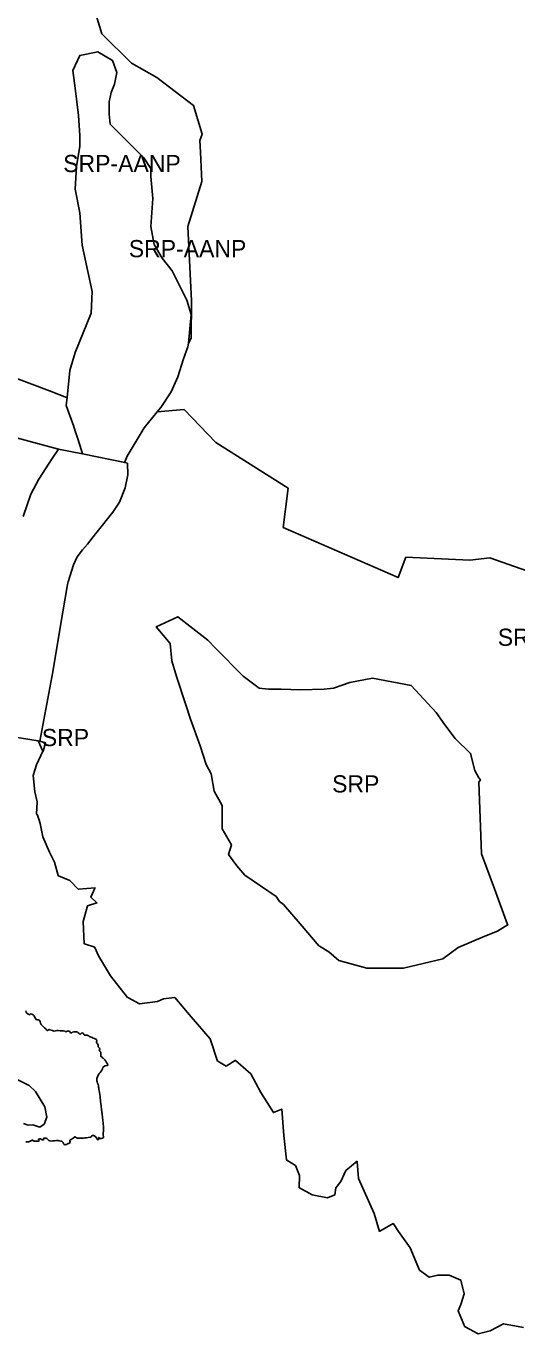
# Model space of a CAD drawing. Extents: x 598968 to 613553, y 4409678 to 4430833.
# Drawn here: x 602505 to 602848, y 4409678 to 4410591 of the extents above; entities that cross this region are included whole.
import ezdxf

# ---------------------------------------------------------------- set-up
doc = ezdxf.new("R2010")
doc.units = 0
for name, color, linetype in [('1', 7, 'Continuous'), ('Sòl Rústic Protegit', 7, 'Continuous'), ('Sòl Rústic Protegit - Alt Nivell de Protecció', 7, 'Continuous')]:
    doc.layers.add(name, color=color, linetype=linetype)

msp = doc.modelspace()

# ---------------------------------------------------------------- linework, layer by layer
at = {"layer": '1'}
for points in [[(602497.7035, 4410094.9206), (602513.6544, 4410092.2408), (602514.8283, 4410092.0436), (602523.893, 4410140.448), (602529.3381, 4410172.8446), (602533.8915, 4410200.156), (602534.0976, 4410201.3922), (602534.6887, 4410203.333), (602538.2975, 4410215.182), (602540.9874, 4410220.802), (602544.5974, 4410225.622), (602548.1209, 4410229.6975), (602553.7417, 4410236.921), (602554.8294, 4410238.3188), (602565.867, 4410252.0322), (602569.4816, 4410257.6212), (602570.4375, 4410259.0991), (602574.4065, 4410269.0133), (602576.2733, 4410278.0161), (602576.0051, 4410286.2359), (602574.1695, 4410286.6131), (602544.6902, 4410292.6714), (602527.955, 4410296.1106), (602523.5834, 4410289.4568), (602518.8825, 4410282.3021), (602514.1639, 4410275.1202), (602508.7008, 4410264.5001), (602503.3766, 4410249.1016)], [(602503.3766, 4410249.1016), (602508.7008, 4410264.5001), (602514.1639, 4410275.1202), (602518.8825, 4410282.3021), (602523.5834, 4410289.4568), (602527.955, 4410296.1106), (602498.704, 4410303.9698)], [(602505.1992, 4409812.3078), (602506.0392, 4409812.2679), (602506.9492, 4409812.3179), (602507.7192, 4409812.4779), (602508.5692, 4409813.0279), (602509.4491, 4409813.4279), (602509.6391, 4409813.4579), (602510.0891, 4409813.5079), (602510.2852, 4409813.3385), (602510.3091, 4409813.3179), (602510.5891, 4409812.7679), (602510.7619, 4409812.7466), (602511.3191, 4409812.678), (602512.199, 4409812.678), (602513.119, 4409812.698), (602513.659, 4409812.758), (602514.329, 4409812.898), (602514.239, 4409813.458), (602513.879, 4409813.788), (602513.929, 4409814.068), (602514.229, 4409814.178), (602514.949, 4409814.418), (602515.419, 4409814.3281), (602515.989, 4409813.9781), (602516.579, 4409813.7381), (602517.189, 4409813.6581), (602517.709, 4409813.8981), (602517.579, 4409814.4281), (602517.559, 4409814.6682), (602517.839, 4409814.7882), (602518.589, 4409814.9382), (602519.359, 4409814.9082), (602519.879, 4409814.5782), (602519.8928, 4409814.5611), (602520.449, 4409813.8782), (602521.139, 4409813.3182), (602521.2443, 4409813.268), (602521.7889, 4409813.0082), (602522.8289, 4409812.8483), (602523.8989, 4409812.9083), (602525.2488, 4409813.0883), (602526.5188, 4409813.2283), (602527.6588, 4409813.1383), (602528.4288, 4409812.9584), (602529.4688, 4409812.8384), (602530.3188, 4409812.6884), (602530.5273, 4409812.5308), (602530.7688, 4409812.3484), (602531.0788, 4409811.7485), (602531.4588, 4409810.8885), (602531.8788, 4409810.3585), (602532.0192, 4409810.3271), (602532.5487, 4409810.2085), (602533.1587, 4409810.4185), (602533.8287, 4409810.5085), (602534.1787, 4409810.7785), (602534.6587, 4409811.0085), (602535.1987, 4409811.0985), (602535.6687, 4409811.3985), (602535.9587, 4409812.1285), (602535.8487, 4409812.7885), (602535.7687, 4409813.3485), (602535.9887, 4409813.6285), (602536.4787, 4409813.7385), (602536.8387, 4409813.8885), (602537.5287, 4409814.2786), (602538.1787, 4409814.7887), (602539.3487, 4409815.8287), (602539.5666, 4409815.6398), (602539.6486, 4409815.5687), (602539.8333, 4409815.4574), (602540.3786, 4409815.1287), (602541.2086, 4409814.9088), (602542.1586, 4409814.8288), (602543.2586, 4409814.7688), (602544.3086, 4409814.8188), (602545.3486, 4409814.8488), (602546.3686, 4409814.9889), (602547.4686, 4409815.1389), (602548.5586, 4409815.2989), (602550.5185, 4409815.649), (602550.6685, 4409815.909), (602550.8785, 4409816.129), (602551.6785, 4409816.589), (602552.2485, 4409816.779), (602552.7085, 4409816.559), (602552.861, 4409816.4392), (602553.2684, 4409816.119), (602553.3397, 4409816.0917), (602553.7384, 4409815.939), (602553.8646, 4409815.8205), (602554.4084, 4409815.309), (602554.5484, 4409814.9291), (602554.7884, 4409814.379), (602555.1084, 4409813.889), (602555.5084, 4409813.599), (602555.5165, 4409813.6069), (602555.9484, 4409814.029), (602556.0684, 4409814.6191), (602555.8684, 4409815.1891), (602555.8784, 4409815.2891), (602555.9684, 4409815.2691), (602556.2033, 4409815.107), (602556.2584, 4409815.0691), (602556.7284, 4409814.7391), (602556.8387, 4409814.6698), (602557.1584, 4409814.469), (602557.7584, 4409814.5091), (602558.5784, 4409814.8092), (602559.2884, 4409815.2892), (602559.4084, 4409815.9092), (602559.2184, 4409816.9892), (602559.1884, 4409818.0092), (602559.1784, 4409818.4891), (602559.2484, 4409819.6191), (602559.3584, 4409820.6791), (602559.3784, 4409822.0991), (602559.3184, 4409823.329), (602559.1784, 4409824.609), (602559.0384, 4409825.699), (602558.9184, 4409826.689), (602558.8384, 4409827.759), (602558.7284, 4409828.829), (602558.6084, 4409829.8689), (602558.4384, 4409830.9389), (602558.3384, 4409831.9589), (602557.9284, 4409834.5088), (602557.6084, 4409837.4388), (602557.1784, 4409840.3787), (602556.9584, 4409843.9886), (602556.5884, 4409846.6686), (602556.4084, 4409847.7786), (602556.1784, 4409848.7486), (602555.9984, 4409849.6486), (602555.9184, 4409850.4985), (602555.7784, 4409851.3485), (602555.5084, 4409852.1985), (602555.2584, 4409853.2185), (602554.9284, 4409854.2284), (602554.6884, 4409854.8884), (602554.6184, 4409855.5184), (602554.7084, 4409856.5484), (602555.1384, 4409857.7384), (602555.5583, 4409858.7284), (602556.0483, 4409859.5784), (602556.3883, 4409859.9784), (602557.0683, 4409860.7984), (602557.7383, 4409861.6284), (602558.2182, 4409862.3884), (602558.5582, 4409863.2684), (602558.9582, 4409864.1584), (602560.2782, 4409865.4384), (602562.2082, 4409865.6784), (602562.2482, 4409866.1784), (602561.9382, 4409866.9184), (602561.4882, 4409867.6984), (602560.9782, 4409868.5684), (602560.3582, 4409869.5483), (602559.6482, 4409870.3083), (602559.0482, 4409870.8083), (602558.4347, 4409871.2705), (602558.3182, 4409871.3582), (602557.9836, 4409871.5554), (602557.7582, 4409871.6882), (602557.5082, 4409872.0682), (602557.5582, 4409872.8182), (602557.5882, 4409873.9182), (602557.3782, 4409874.9982), (602556.8282, 4409875.6982), (602556.4082, 4409876.2281), (602556.5482, 4409876.4381), (602556.6882, 4409877.1281), (602556.4582, 4409877.7481), (602556.0582, 4409878.2081), (602555.6082, 4409878.698), (602555.6382, 4409879.108), (602555.5482, 4409880.048), (602555.1982, 4409880.698), (602554.7182, 4409881.098), (602554.3682, 4409881.778), (602554.4382, 4409882.038), (602554.6082, 4409882.668), (602554.4725, 4409883.6278), (602554.4682, 4409883.658), (602553.9082, 4409883.9679), (602553.0783, 4409884.3479), (602552.1983, 4409884.6779), (602551.3483, 4409885.0578), (602550.7383, 4409885.3378), (602550.0584, 4409885.5578), (602549.5636, 4409885.797), (602549.4584, 4409885.8478), (602548.9872, 4409886.2263), (602548.8484, 4409886.3378), (602547.9484, 4409886.7778), (602547.2784, 4409886.8577), (602546.6784, 4409886.6777), (602546.1786, 4409886.7277), (602546.0784, 4409886.7377), (602545.7184, 4409887.1177), (602545.4784, 4409887.7777), (602545.1589, 4409888.1406), (602545.0384, 4409888.2776), (602544.2884, 4409888.4376), (602543.7984, 4409888.0276), (602543.3184, 4409887.5776), (602542.8284, 4409887.5676), (602542.411, 4409887.8373), (602542.1784, 4409887.9876), (602541.5679, 4409888.6073), (602541.5184, 4409888.6576), (602540.8784, 4409889.0276), (602539.8585, 4409889.1475), (602538.6985, 4409889.0675), (602537.7385, 4409888.8474), (602537.1485, 4409888.4374), (602536.602, 4409888.3209), (602536.5386, 4409888.3074), (602536.1886, 4409888.6474), (602535.761, 4409889.279), (602535.7486, 4409889.2974), (602535.2186, 4409889.6274), (602534.4086, 4409889.7074), (602533.5086, 4409889.4374), (602533.2386, 4409889.2874), (602532.8368, 4409889.209), (602532.8286, 4409889.2074), (602532.5948, 4409889.3699), (602532.3686, 4409889.5273), (602531.2986, 4409889.8673), (602530.1686, 4409889.9073), (602529.0786, 4409889.8672), (602527.7986, 4409890.0472), (602526.9887, 4409890.1272), (602525.8587, 4409889.7972), (602524.7987, 4409889.5872), (602524.2987, 4409889.7971), (602523.7788, 4409889.9771), (602522.8188, 4409890.2871), (602521.9488, 4409890.587), (602521.3388, 4409890.767), (602520.8388, 4409890.487), (602520.5688, 4409890.087), (602520.2888, 4409890.057), (602519.9029, 4409890.2669), (602519.7188, 4409890.367), (602519.0288, 4409891.077), (602518.2588, 4409891.887), (602517.7988, 4409892.307), (602516.9888, 4409893.0369), (602516.1988, 4409893.7769), (602515.8388, 4409894.2168), (602515.3388, 4409895.2168), (602515.1088, 4409896.1968), (602514.683, 4409897.0116), (602514.6488, 4409897.0768), (602513.9588, 4409897.3968), (602513.0789, 4409897.3668), (602512.5318, 4409897.6001), (602512.3289, 4409897.6867), (602512.0289, 4409898.2267), (602511.4689, 4409899.1667), (602510.8389, 4409900.2366), (602510.1971, 4409901.0222), (602510.1689, 4409901.0566), (602509.3589, 4409901.5366), (602508.469, 4409901.5766), (602507.819, 4409901.3066), (602507.479, 4409901.0566), (602506.9678, 4409901.3312), (602506.809, 4409901.4165), (602505.639, 4409902.4665), (602505.409, 4409902.8665), (602505.059, 4409903.6964)], [(602503.5749, 4409825.1934), (602506.781, 4409823.887), (602510.038, 4409824.0952), (602514.9767, 4409822.5157), (602517.8562, 4409824.5582), (602519.8539, 4409829.508), (602518.491, 4409836.7592), (602511.9685, 4409847.5069), (602507.4339, 4409851.5941), (602492.1202, 4409859.2992)], [(602492.1202, 4409859.2992), (602507.4339, 4409851.5941), (602511.9685, 4409847.5069), (602518.491, 4409836.7592), (602519.8539, 4409829.508), (602517.8562, 4409824.5582), (602514.9767, 4409822.5157), (602510.038, 4409824.0952), (602506.781, 4409823.887), (602503.5749, 4409825.1934)]]:
    msp.add_lwpolyline(points, dxfattribs=at)
at = {"layer": 'Sòl Rústic Protegit'}
for points in [[(602551.6801, 4410607.5098), (602558.2427, 4410586.0098), (602578.8677, 4410565.5098), (602596.4927, 4410555.5098), (602622.1801, 4410536.0098), (602628.1177, 4410516.0098), (602626.4927, 4410511.5098), (602626.9301, 4410503.5098), (602627.9927, 4410483.0098), (602618.2427, 4410451.5098), (602620.8677, 4410399.5098), (602620.5551, 4410373.5098), (602618.5551, 4410370.01), (602618.3049, 4410367.5102), (602615.1799, 4410359.0102), (602611.2425, 4410346.5102), (602606.4927, 4410336.0102), (602599.4299, 4410325.0102), (602596.8051, 4410322.01), (602615.7179, 4410323.687), (602637.6591, 4410300.6488), (602688.1239, 4410268.834), (602684.8327, 4410241.4076), (602764.9183, 4410206.3016), (602770.4035, 4410220.5634), (602814.9301, 4410218.5098), (602828.9301, 4410220.0098), (602868.0419, 4410206.3016)], [(602498.704, 4410303.9698), (602527.955, 4410296.1106), (602544.6902, 4410292.6714), (602544.6045, 4410293.0698), (602544.5015, 4410293.4478), (602544.4605, 4410293.598), (602544.4255, 4410293.7078), (602544.0095, 4410295.0066), (602541.3741, 4410303.2372), (602540.2537, 4410306.7368), (602539.9075, 4410307.8178), (602538.8939, 4410310.9834), (602538.6689, 4410311.6864), (602538.6473, 4410311.754), (602538.6361, 4410311.7888), (602538.6301, 4410311.8072), (602538.6273, 4410311.8164), (602533.3677, 4410326.5102), (602533.9301, 4410332.01), (602533.4921, 4410332.1754), (602533.4929, 4410332.1842), (602521.5571, 4410336.6864), (602444.8719, 4410365.6686)]]:
    msp.add_lwpolyline(points, dxfattribs=at)
for points in [[(602668.0551, 4410129.0098), (602656.8677, 4410137.5098), (602637.5551, 4410157.0098), (602632.2427, 4410162.5098), (602611.1801, 4410179.0098), (602596.1177, 4410172.0098), (602605.8443, 4410160.225), (602606.9413, 4410148.1574), (602610.2325, 4410137.1868), (602616.8149, 4410117.4396), (602620.1061, 4410107.566), (602626.6885, 4410088.916), (602631.0767, 4410075.7512), (602634.3679, 4410069.169), (602636.5621, 4410057.1012), (602642.0473, 4410047.2278), (602642.0473, 4410039.5482), (602642.0473, 4410030.7718), (602648.6297, 4410019.8012), (602646.6801, 4410013.0098), (602649.8677, 4410008.5098), (602652.4927, 4410005.0098), (602657.9301, 4409998.5098), (602679.8051, 4409983.5098), (602682.2427, 4409980.0098), (602685.0551, 4409978.0098), (602696.5551, 4409964.5098), (602709.8677, 4409949.0098), (602709.9927, 4409949.0098), (602716.5551, 4409945.0098), (602723.6177, 4409939.0098), (602743.1801, 4409933.5098), (602768.6801, 4409933.5098), (602796.1177, 4409940.0098), (602806.9301, 4409948.0098), (602825.5551, 4409956.0098), (602834.3677, 4409959.5098), (602841.6801, 4409964.0098), (602841.3051, 4409964.0098), (602832.1177, 4409989.0098), (602823.2427, 4410013.5098), (602821.3677, 4410063.5098), (602822.4301, 4410065.0098), (602821.2427, 4410066.5098), (602818.4927, 4410071.5098), (602815.4927, 4410083.5098), (602804.8677, 4410094.0098), (602797.4927, 4410103.5098), (602791.4301, 4410112.0098), (602774.1177, 4410131.0098), (602747.0551, 4410136.0098), (602731.1801, 4410133.0098), (602719.8051, 4410129.0098), (602713.4301, 4410128.5098), (602696.8677, 4410128.0098), (602683.4301, 4410128.5098), (602674.4301, 4410128.5098)], [(602514.8283, 4410092.0436), (602513.6544, 4410092.2408), (602516.9967, 4410085.1718), (602516.9297, 4410085.0264), (602517.2427, 4410085.0098), (602518.9569, 4410090.8518)]]:
    msp.add_lwpolyline(points, close=True, dxfattribs=at)
at = {"layer": 'Sòl Rústic Protegit - Alt Nivell de Protecció'}
for points in [[(602444.8719, 4410365.6686), (602521.5571, 4410336.6864), (602533.4929, 4410332.1842), (602533.4921, 4410332.1754), (602533.9301, 4410332.01), (602535.7427, 4410351.01), (602539.6801, 4410363.51), (602550.6801, 4410391.01), (602551.4301, 4410406.01), (602548.3051, 4410420.01), (602544.3677, 4410438.51), (602542.8051, 4410461.01), (602539.6801, 4410477.51), (602540.4301, 4410493.51), (602542.8051, 4410507.51), (602542.7427, 4410515.01), (602541.9301, 4410529.01), (602539.6177, 4410548.01), (602537.9927, 4410560.51), (602542.7427, 4410571.01), (602555.3051, 4410573.51), (602565.5551, 4410567.51), (602568.6801, 4410559.01), (602567.1177, 4410551.01), (602564.7427, 4410545.01), (602563.1801, 4410538.51), (602563.1801, 4410530.01), (602563.9927, 4410523.01), (602575.7427, 4410511.01), (602587.5551, 4410499.51), (602592.3051, 4410492.01), (602592.3051, 4410486.51), (602593.8677, 4410471.01), (602592.3051, 4410451.51), (602594.6801, 4410439.01), (602600.1801, 4410429.51), (602607.2427, 4410420.51), (602617.4301, 4410400.01), (602620.6177, 4410390.01), (602618.5551, 4410370.01), (602620.5551, 4410373.5098), (602620.8677, 4410399.5098), (602618.2427, 4410451.5098), (602627.9927, 4410483.0098), (602626.9301, 4410503.5098), (602626.4927, 4410511.5098), (602628.1177, 4410516.0098), (602622.1801, 4410536.0098), (602596.4927, 4410555.5098), (602578.8677, 4410565.5098), (602558.2427, 4410586.0098), (602551.6801, 4410607.5098)], [(602868.0419, 4410206.3016), (602828.9301, 4410220.0098), (602814.9301, 4410218.5098), (602770.4035, 4410220.5634), (602764.9183, 4410206.3016), (602684.8327, 4410241.4076), (602688.1239, 4410268.834), (602637.6591, 4410300.6488), (602615.7179, 4410323.687), (602596.8051, 4410322.01), (602587.6177, 4410311.01), (602575.8677, 4410291.01), (602574.3077, 4410287.0842), (602574.1695, 4410286.6131), (602576.0051, 4410286.2359), (602576.2733, 4410278.0161), (602574.4065, 4410269.0133), (602570.4375, 4410259.0991), (602569.4816, 4410257.6212), (602565.867, 4410252.0322), (602554.8294, 4410238.3188), (602553.7417, 4410236.921), (602548.1209, 4410229.6975), (602544.5974, 4410225.622), (602540.9874, 4410220.802), (602538.2975, 4410215.182), (602534.6887, 4410203.333), (602534.0976, 4410201.3922), (602533.8915, 4410200.156), (602529.3381, 4410172.8446), (602523.893, 4410140.448), (602514.8283, 4410092.0436), (602518.9569, 4410090.8518), (602517.2427, 4410085.0098), (602516.9297, 4410085.0264), (602512.6217, 4410075.6718), (602510.2467, 4410068.1718), (602511.4343, 4410056.672), (602512.9967, 4410049.672), (602512.6843, 4410041.1722), (602512.8129, 4410040.812), (602513.1843, 4410040.6722), (602513.2385, 4410040.5098), (602514.2169, 4410037.5748), (602515.1843, 4410034.6722), (602516.9967, 4410025.1722), (602521.6843, 4410014.6724), (602525.1217, 4410007.6726), (602527.6843, 4409998.1726), (602527.9125, 4409998.0758), (602535.9341, 4409994.6728), (602536.0307, 4409994.5732), (602541.7467, 4409988.6728), (602541.8279, 4409988.6798), (602553.4341, 4409989.673), (602553.3455, 4409989.477), (602550.4965, 4409983.173), (602554.7465, 4409979.1732), (602548.2467, 4409977.173), (602545.0591, 4409966.1732), (602545.7467, 4409950.6732), (602545.9873, 4409950.5924), (602553.1841, 4409948.1734), (602553.2277, 4409948.0716), (602555.7465, 4409942.1734), (602564.1215, 4409928.1736), (602576.0589, 4409913.174), (602576.2607, 4409913.0656), (602584.4339, 4409908.674), (602596.9963, 4409910.1742), (602601.1837, 4409912.1742), (602608.8713, 4409913.1744), (602609.0229, 4409912.9976), (602620.4337, 4409899.6746), (602633.7461, 4409884.1748), (602638.9961, 4409868.675), (602639.2343, 4409868.5346), (602644.9335, 4409865.1752), (602651.1835, 4409869.1752), (602651.3997, 4409868.9896), (602662.2459, 4409859.6754), (602669.2459, 4409846.6756), (602677.8709, 4409832.6758), (602677.9855, 4409832.7246), (602683.7457, 4409835.1758), (602683.7607, 4409834.9916), (602685.2457, 4409816.676), (602687.0581, 4409799.6762), (602687.3041, 4409799.5204), (602693.3705, 4409795.6762), (602693.3769, 4409795.6596), (602696.0581, 4409788.6762), (602695.8705, 4409780.1764), (602696.1187, 4409780.0386), (602704.8703, 4409775.1764), (602715.7453, 4409773.1766), (602720.7453, 4409775.1766), (602721.3703, 4409780.1766), (602724.8703, 4409784.6766), (602728.4327, 4409792.1766), (602736.3077, 4409798.6768), (602736.3367, 4409798.3296), (602737.3077, 4409786.6768), (602748.3075, 4409762.177), (602752.0573, 4409749.6772), (602752.2257, 4409749.7748), (602761.5573, 4409755.1772), (602761.7031, 4409754.9522), (602765.1197, 4409749.6774), (602773.3697, 4409738.1776), (602779.8069, 4409722.6776), (602786.6819, 4409717.6778), (602786.6947, 4409717.6811), (602792.5569, 4409719.1778), (602800.6817, 4409719.178), (602808.6817, 4409715.678), (602808.6989, 4409715.6072), (602810.9941, 4409706.1782), (602808.8067, 4409698.6782), (602806.8691, 4409694.1782), (602811.5565, 4409683.1782), (602811.7861, 4409683.0532), (602820.7439, 4409678.1784), (602829.3063, 4409680.1786), (602838.5563, 4409685.1786), (602852.3687, 4409682.6788)]]:
    msp.add_lwpolyline(points, dxfattribs=at)
for points in [[(602618.5551, 4410370.01), (602620.6177, 4410390.01), (602617.4301, 4410400.01), (602607.2427, 4410420.51), (602600.1801, 4410429.51), (602594.6801, 4410439.01), (602592.3051, 4410451.51), (602593.8677, 4410471.01), (602592.3051, 4410486.51), (602592.3051, 4410492.01), (602587.5551, 4410499.51), (602575.7427, 4410511.01), (602563.9927, 4410523.01), (602563.1801, 4410530.01), (602563.1801, 4410538.51), (602564.7427, 4410545.01), (602567.1177, 4410551.01), (602568.6801, 4410559.01), (602565.5551, 4410567.51), (602555.3051, 4410573.51), (602542.7427, 4410571.01), (602537.9927, 4410560.51), (602539.6177, 4410548.01), (602541.9301, 4410529.01), (602542.7427, 4410515.01), (602542.8051, 4410507.51), (602540.4301, 4410493.51), (602539.6801, 4410477.51), (602542.8051, 4410461.01), (602544.3677, 4410438.51), (602548.3051, 4410420.01), (602551.4301, 4410406.01), (602550.6801, 4410391.01), (602539.6801, 4410363.51), (602535.7427, 4410351.01), (602533.9301, 4410332.01), (602533.3677, 4410326.5102), (602538.6273, 4410311.8164), (602538.6301, 4410311.8072), (602538.6361, 4410311.7888), (602538.6473, 4410311.754), (602538.6689, 4410311.6864), (602538.8939, 4410310.9834), (602539.9075, 4410307.8178), (602540.2537, 4410306.7368), (602541.3741, 4410303.2372), (602544.0095, 4410295.0066), (602544.4255, 4410293.7078), (602544.4605, 4410293.598), (602544.5015, 4410293.4478), (602544.6045, 4410293.0698), (602544.6902, 4410292.6714), (602574.1695, 4410286.6131), (602574.3077, 4410287.0842), (602575.8677, 4410291.01), (602587.6177, 4410311.01), (602596.8051, 4410322.01), (602599.4299, 4410325.0102), (602606.4927, 4410336.0102), (602611.2425, 4410346.5102), (602615.1799, 4410359.0102), (602618.3049, 4410367.5102)], [(602668.0551, 4410129.0098), (602674.4301, 4410128.5098), (602683.4301, 4410128.5098), (602696.8677, 4410128.0098), (602713.4301, 4410128.5098), (602719.8051, 4410129.0098), (602731.1801, 4410133.0098), (602747.0551, 4410136.0098), (602774.1177, 4410131.0098), (602791.4301, 4410112.0098), (602797.4927, 4410103.5098), (602804.8677, 4410094.0098), (602815.4927, 4410083.5098), (602818.4927, 4410071.5098), (602821.2427, 4410066.5098), (602822.4301, 4410065.0098), (602821.3677, 4410063.5098), (602823.2427, 4410013.5098), (602832.1177, 4409989.0098), (602841.3051, 4409964.0098), (602841.6801, 4409964.0098), (602834.3677, 4409959.5098), (602825.5551, 4409956.0098), (602806.9301, 4409948.0098), (602796.1177, 4409940.0098), (602768.6801, 4409933.5098), (602743.1801, 4409933.5098), (602723.6177, 4409939.0098), (602716.5551, 4409945.0098), (602709.9927, 4409949.0098), (602709.8677, 4409949.0098), (602696.5551, 4409964.5098), (602685.0551, 4409978.0098), (602682.2427, 4409980.0098), (602679.8051, 4409983.5098), (602657.9301, 4409998.5098), (602652.4927, 4410005.0098), (602649.8677, 4410008.5098), (602646.6801, 4410013.0098), (602648.6297, 4410019.8012), (602642.0473, 4410030.7718), (602642.0473, 4410039.5482), (602642.0473, 4410047.2278), (602636.5621, 4410057.1012), (602634.3679, 4410069.169), (602631.0767, 4410075.7512), (602626.6885, 4410088.916), (602620.1061, 4410107.566), (602616.8149, 4410117.4396), (602610.2325, 4410137.1868), (602606.9413, 4410148.1574), (602605.8443, 4410160.225), (602596.1177, 4410172.0098), (602611.1801, 4410179.0098), (602632.2427, 4410162.5098), (602637.5551, 4410157.0098), (602656.8677, 4410137.5098)]]:
    msp.add_lwpolyline(points, close=True, dxfattribs=at)

# ---------------------------------------------------------------- texts
at = {"layer": 'Sòl Rústic Protegit'}
for p in [(602516.3056, 4410088.6253), (602718.8989, 4410056.2598)]:
    msp.add_text('SRP', height=12, dxfattribs=at).set_placement(p)
at = {"layer": 'Sòl Rústic Protegit - Alt Nivell de Protecció'}
for p in [(602531.2114, 4410489.5099), (602576.9927, 4410430.0615), (602834.5044, 4410158.6703)]:
    msp.add_text('SRP-AANP', height=12, dxfattribs=at).set_placement(p)

doc.saveas('drawing.dxf')
